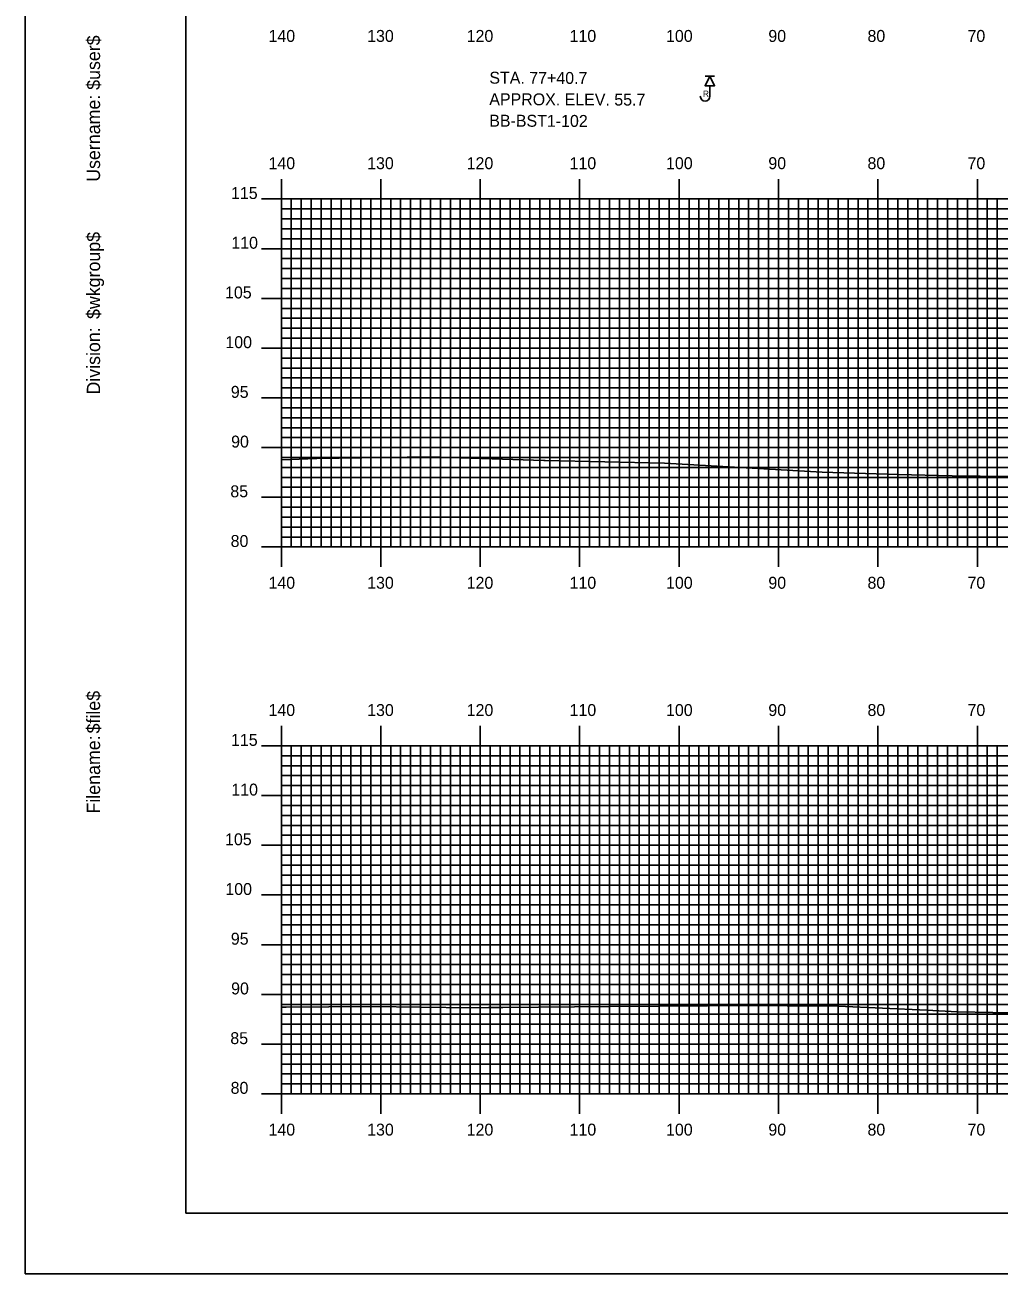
# Model space of a CAD drawing. Extents: x 1761791 to 1762134, y 442591 to 442811.
# Drawn here: x 1761791 to 1761888.9, y 442590.5 to 442716.2 of the extents above; entities that cross this region are included whole.
import ezdxf

# ---------------------------------------------------------------- set-up
doc = ezdxf.new("R2010")
doc.units = 0
for name, color, linetype in [('BORDER', 7, 'Continuous'), ('BORING - REFUSAL', 7, 'Continuous'), ('H_V ANNOTATION', 7, 'Continuous'), ('MAJOR', 7, 'Continuous'), ('MINOR', 7, 'Continuous'), ('PLOT BOUNDARY', 7, 'Continuous'), ('S_Roadway_Centerline', 7, 'Continuous')]:
    doc.layers.add(name, color=color, linetype=linetype)

msp = doc.modelspace()

# ---------------------------------------------------------------- linework, layer by layer
at = {"layer": 'BORDER'}
msp.add_lwpolyline([(1761807.15, 442596.67), (1762127.15, 442596.67), (1762127.15, 442806.67), (1761807.15, 442806.67)], close=True, dxfattribs=at)
at = {"layer": 'BORING - REFUSAL'}
for p, q in [((1761860.33, 442711.02), (1761859.37, 442711.02)), ((1761859.85, 442710.06), (1761859.85, 442709))]:
    msp.add_line(p, q, dxfattribs=at)
msp.add_lwpolyline([(1761859.85, 442711.02), (1761860.33, 442710.06), (1761859.37, 442710.06)], close=True, dxfattribs=at)
msp.add_arc((1761859.37, 442709), 0.485, 180, 0, dxfattribs=at)
at = {"layer": 'MAJOR'}
for p, q in [((1761816.75, 442700.67), (1761816.75, 442698.67)), ((1761826.75, 442700.67), (1761826.75, 442698.67)), ((1761836.75, 442700.67), (1761836.75, 442698.67)), ((1761846.75, 442700.67), (1761846.75, 442698.67)), ((1761856.75, 442700.67), (1761856.75, 442698.67)), ((1761866.75, 442700.67), (1761866.75, 442698.67)), ((1761876.75, 442700.67), (1761876.75, 442698.67)), ((1761886.75, 442700.67), (1761886.75, 442698.67)), ((1761814.75, 442698.67), (1761816.75, 442698.67)), ((1761816.75, 442698.67), (1762096.75, 442698.67)), ((1761816.75, 442663.67), (1761816.75, 442698.67)), ((1761816.75, 442663.67), (1761816.75, 442698.67)), ((1761816.75, 442698.67), (1762096.75, 442698.67)), ((1761826.75, 442663.67), (1761826.75, 442698.67)), ((1761836.75, 442663.67), (1761836.75, 442698.67)), ((1761846.75, 442663.67), (1761846.75, 442698.67)), ((1761856.75, 442663.67), (1761856.75, 442698.67)), ((1761866.75, 442663.67), (1761866.75, 442698.67)), ((1761876.75, 442663.67), (1761876.75, 442698.67)), ((1761886.75, 442663.67), (1761886.75, 442698.67)), ((1761814.75, 442693.67), (1761816.75, 442693.67)), ((1761816.75, 442693.67), (1762096.75, 442693.67)), ((1761814.75, 442688.67), (1761816.75, 442688.67)), ((1761816.75, 442688.67), (1762096.75, 442688.67)), ((1761814.75, 442683.67), (1761816.75, 442683.67)), ((1761816.75, 442683.67), (1762096.75, 442683.67)), ((1761814.75, 442678.67), (1761816.75, 442678.67)), ((1761816.75, 442678.67), (1762096.75, 442678.67)), ((1761814.75, 442673.67), (1761816.75, 442673.67)), ((1761816.75, 442673.67), (1762096.75, 442673.67)), ((1761814.75, 442668.67), (1761816.75, 442668.67)), ((1761816.75, 442668.67), (1762096.75, 442668.67)), ((1761814.75, 442663.67), (1761816.75, 442663.67)), ((1761816.75, 442663.67), (1762096.75, 442663.67)), ((1761816.75, 442663.67), (1762096.75, 442663.67)), ((1761816.75, 442661.66), (1761816.75, 442663.67)), ((1761826.75, 442661.66), (1761826.75, 442663.67)), ((1761836.75, 442661.66), (1761836.75, 442663.67)), ((1761846.75, 442661.66), (1761846.75, 442663.67)), ((1761856.75, 442661.66), (1761856.75, 442663.67)), ((1761866.75, 442661.66), (1761866.75, 442663.67)), ((1761876.75, 442661.66), (1761876.75, 442663.67)), ((1761886.75, 442661.66), (1761886.75, 442663.67)), ((1761816.75, 442645.67), (1761816.75, 442643.67)), ((1761826.75, 442645.67), (1761826.75, 442643.67)), ((1761836.75, 442645.67), (1761836.75, 442643.67)), ((1761846.75, 442645.67), (1761846.75, 442643.67)), ((1761856.75, 442645.67), (1761856.75, 442643.67)), ((1761866.75, 442645.67), (1761866.75, 442643.67)), ((1761876.75, 442645.67), (1761876.75, 442643.67)), ((1761886.75, 442645.67), (1761886.75, 442643.67)), ((1761814.75, 442643.67), (1761816.75, 442643.67)), ((1761816.75, 442643.67), (1762096.75, 442643.67)), ((1761816.75, 442608.67), (1761816.75, 442643.67)), ((1761816.75, 442608.67), (1761816.75, 442643.67)), ((1761816.75, 442643.67), (1762096.75, 442643.67)), ((1761826.75, 442608.67), (1761826.75, 442643.67)), ((1761836.75, 442608.67), (1761836.75, 442643.67)), ((1761846.75, 442608.67), (1761846.75, 442643.67)), ((1761856.75, 442608.67), (1761856.75, 442643.67)), ((1761866.75, 442608.67), (1761866.75, 442643.67)), ((1761876.75, 442608.67), (1761876.75, 442643.67)), ((1761886.75, 442608.67), (1761886.75, 442643.67)), ((1761814.75, 442638.67), (1761816.75, 442638.67)), ((1761816.75, 442638.67), (1762096.75, 442638.67)), ((1761814.75, 442633.67), (1761816.75, 442633.67)), ((1761816.75, 442633.67), (1762096.75, 442633.67)), ((1761814.75, 442628.67), (1761816.75, 442628.67)), ((1761816.75, 442628.67), (1762096.75, 442628.67)), ((1761814.75, 442623.67), (1761816.75, 442623.67)), ((1761816.75, 442623.67), (1762096.75, 442623.67)), ((1761814.75, 442618.67), (1761816.75, 442618.67)), ((1761816.75, 442618.67), (1762096.75, 442618.67)), ((1761814.75, 442613.67), (1761816.75, 442613.67)), ((1761816.75, 442613.67), (1762096.75, 442613.67)), ((1761814.75, 442608.67), (1761816.75, 442608.67)), ((1761816.75, 442608.67), (1762096.75, 442608.67)), ((1761816.75, 442608.67), (1762096.75, 442608.67)), ((1761816.75, 442606.66), (1761816.75, 442608.67)), ((1761826.75, 442606.66), (1761826.75, 442608.67)), ((1761836.75, 442606.66), (1761836.75, 442608.67)), ((1761846.75, 442606.66), (1761846.75, 442608.67)), ((1761856.75, 442606.66), (1761856.75, 442608.67)), ((1761866.75, 442606.66), (1761866.75, 442608.67)), ((1761876.75, 442606.66), (1761876.75, 442608.67)), ((1761886.75, 442606.66), (1761886.75, 442608.67))]:
    msp.add_line(p, q, dxfattribs=at)
at = {"layer": 'MINOR'}
for p, q in [((1761817.75, 442663.67), (1761817.75, 442698.67)), ((1761818.75, 442663.67), (1761818.75, 442698.67)), ((1761819.75, 442663.67), (1761819.75, 442698.67)), ((1761820.75, 442663.67), (1761820.75, 442698.67)), ((1761821.75, 442663.67), (1761821.75, 442698.67)), ((1761822.75, 442663.67), (1761822.75, 442698.67)), ((1761823.75, 442663.67), (1761823.75, 442698.67)), ((1761824.75, 442663.67), (1761824.75, 442698.67)), ((1761825.75, 442663.67), (1761825.75, 442698.67)), ((1761827.75, 442663.67), (1761827.75, 442698.67)), ((1761828.75, 442663.67), (1761828.75, 442698.67)), ((1761829.75, 442663.67), (1761829.75, 442698.67)), ((1761830.75, 442663.67), (1761830.75, 442698.67)), ((1761831.75, 442663.67), (1761831.75, 442698.67)), ((1761832.75, 442663.67), (1761832.75, 442698.67)), ((1761833.75, 442663.67), (1761833.75, 442698.67)), ((1761834.75, 442663.67), (1761834.75, 442698.67)), ((1761835.75, 442663.67), (1761835.75, 442698.67)), ((1761837.75, 442663.67), (1761837.75, 442698.67)), ((1761838.75, 442663.67), (1761838.75, 442698.67)), ((1761839.75, 442663.67), (1761839.75, 442698.67)), ((1761840.75, 442663.67), (1761840.75, 442698.67)), ((1761841.75, 442663.67), (1761841.75, 442698.67)), ((1761842.75, 442663.67), (1761842.75, 442698.67)), ((1761843.75, 442663.67), (1761843.75, 442698.67)), ((1761844.75, 442663.67), (1761844.75, 442698.67)), ((1761845.75, 442663.67), (1761845.75, 442698.67)), ((1761847.75, 442663.67), (1761847.75, 442698.67)), ((1761848.75, 442663.67), (1761848.75, 442698.67)), ((1761849.75, 442663.67), (1761849.75, 442698.67)), ((1761850.75, 442663.67), (1761850.75, 442698.67)), ((1761851.75, 442663.67), (1761851.75, 442698.67)), ((1761852.75, 442663.67), (1761852.75, 442698.67)), ((1761853.75, 442663.67), (1761853.75, 442698.67)), ((1761854.75, 442663.67), (1761854.75, 442698.67)), ((1761855.75, 442663.67), (1761855.75, 442698.67)), ((1761857.75, 442663.67), (1761857.75, 442698.67)), ((1761858.75, 442663.67), (1761858.75, 442698.67)), ((1761859.75, 442663.67), (1761859.75, 442698.67)), ((1761860.75, 442663.67), (1761860.75, 442698.67)), ((1761861.75, 442663.67), (1761861.75, 442698.67)), ((1761862.75, 442663.67), (1761862.75, 442698.67)), ((1761863.75, 442663.67), (1761863.75, 442698.67)), ((1761864.75, 442663.67), (1761864.75, 442698.67)), ((1761865.75, 442663.67), (1761865.75, 442698.67)), ((1761867.75, 442663.67), (1761867.75, 442698.67)), ((1761868.75, 442663.67), (1761868.75, 442698.67)), ((1761869.75, 442663.67), (1761869.75, 442698.67)), ((1761870.75, 442663.67), (1761870.75, 442698.67)), ((1761871.75, 442663.67), (1761871.75, 442698.67)), ((1761872.75, 442663.67), (1761872.75, 442698.67)), ((1761873.75, 442663.67), (1761873.75, 442698.67)), ((1761874.75, 442663.67), (1761874.75, 442698.67)), ((1761875.75, 442663.67), (1761875.75, 442698.67)), ((1761877.75, 442663.67), (1761877.75, 442698.67)), ((1761878.75, 442663.67), (1761878.75, 442698.67)), ((1761879.75, 442663.67), (1761879.75, 442698.67)), ((1761880.75, 442663.67), (1761880.75, 442698.67)), ((1761881.75, 442663.67), (1761881.75, 442698.67)), ((1761882.75, 442663.67), (1761882.75, 442698.67)), ((1761883.75, 442663.67), (1761883.75, 442698.67)), ((1761884.75, 442663.67), (1761884.75, 442698.67)), ((1761885.75, 442663.67), (1761885.75, 442698.67)), ((1761887.75, 442663.67), (1761887.75, 442698.67)), ((1761888.75, 442663.67), (1761888.75, 442698.67)), ((1761816.75, 442697.67), (1762096.75, 442697.67)), ((1761816.75, 442697.67), (1761818.76, 442697.67)), ((1761816.75, 442696.67), (1762096.75, 442696.67)), ((1761816.75, 442696.67), (1761818.76, 442696.67)), ((1761816.75, 442695.67), (1762096.75, 442695.67)), ((1761816.75, 442695.67), (1761818.76, 442695.67)), ((1761816.75, 442694.67), (1762096.75, 442694.67)), ((1761816.75, 442694.67), (1761818.76, 442694.67)), ((1761816.75, 442692.67), (1762096.75, 442692.67)), ((1761816.75, 442692.67), (1761818.76, 442692.67)), ((1761816.75, 442691.67), (1762096.75, 442691.67)), ((1761816.75, 442691.67), (1761818.76, 442691.67)), ((1761816.75, 442690.67), (1762096.75, 442690.67)), ((1761816.75, 442690.67), (1761818.76, 442690.67)), ((1761816.75, 442689.67), (1762096.75, 442689.67)), ((1761816.75, 442689.67), (1761818.76, 442689.67)), ((1761816.75, 442687.67), (1762096.75, 442687.67)), ((1761816.75, 442687.67), (1761818.76, 442687.67)), ((1761816.75, 442686.67), (1762096.75, 442686.67)), ((1761816.75, 442686.67), (1761818.76, 442686.67)), ((1761816.75, 442685.67), (1762096.75, 442685.67)), ((1761816.75, 442685.67), (1761818.76, 442685.67)), ((1761816.75, 442684.67), (1762096.75, 442684.67)), ((1761816.75, 442684.67), (1761818.76, 442684.67)), ((1761816.75, 442682.67), (1762096.75, 442682.67)), ((1761816.75, 442682.67), (1761818.76, 442682.67)), ((1761816.75, 442681.67), (1762096.75, 442681.67)), ((1761816.75, 442681.67), (1761818.76, 442681.67)), ((1761816.75, 442680.67), (1762096.75, 442680.67)), ((1761816.75, 442680.67), (1761818.76, 442680.67)), ((1761816.75, 442679.67), (1762096.75, 442679.67)), ((1761816.75, 442679.67), (1761818.76, 442679.67)), ((1761816.75, 442677.67), (1762096.75, 442677.67)), ((1761816.75, 442677.67), (1761818.76, 442677.67)), ((1761816.75, 442676.67), (1762096.75, 442676.67)), ((1761816.75, 442676.67), (1761818.76, 442676.67)), ((1761816.75, 442675.67), (1762096.75, 442675.67)), ((1761816.75, 442675.67), (1761818.76, 442675.67)), ((1761816.75, 442674.67), (1762096.75, 442674.67)), ((1761816.75, 442674.67), (1761818.76, 442674.67)), ((1761816.75, 442672.67), (1762096.75, 442672.67)), ((1761816.75, 442672.67), (1761818.76, 442672.67)), ((1761816.75, 442671.67), (1762096.75, 442671.67)), ((1761816.75, 442671.67), (1761818.76, 442671.67)), ((1761816.75, 442670.67), (1762096.75, 442670.67)), ((1761816.75, 442670.67), (1761818.76, 442670.67)), ((1761816.75, 442669.67), (1762096.75, 442669.67)), ((1761816.75, 442669.67), (1761818.76, 442669.67)), ((1761816.75, 442667.67), (1762096.75, 442667.67)), ((1761816.75, 442667.67), (1761818.76, 442667.67)), ((1761816.75, 442666.67), (1762096.75, 442666.67)), ((1761816.75, 442666.67), (1761818.76, 442666.67)), ((1761816.75, 442665.67), (1762096.75, 442665.67)), ((1761816.75, 442665.67), (1761818.76, 442665.67)), ((1761816.75, 442664.67), (1762096.75, 442664.67)), ((1761816.75, 442664.67), (1761818.76, 442664.67)), ((1761817.75, 442608.67), (1761817.75, 442643.67)), ((1761818.75, 442608.67), (1761818.75, 442643.67)), ((1761819.75, 442608.67), (1761819.75, 442643.67)), ((1761820.75, 442608.67), (1761820.75, 442643.67)), ((1761821.75, 442608.67), (1761821.75, 442643.67)), ((1761822.75, 442608.67), (1761822.75, 442643.67)), ((1761823.75, 442608.67), (1761823.75, 442643.67)), ((1761824.75, 442608.67), (1761824.75, 442643.67)), ((1761825.75, 442608.67), (1761825.75, 442643.67)), ((1761827.75, 442608.67), (1761827.75, 442643.67)), ((1761828.75, 442608.67), (1761828.75, 442643.67)), ((1761829.75, 442608.67), (1761829.75, 442643.67)), ((1761830.75, 442608.67), (1761830.75, 442643.67)), ((1761831.75, 442608.67), (1761831.75, 442643.67)), ((1761832.75, 442608.67), (1761832.75, 442643.67)), ((1761833.75, 442608.67), (1761833.75, 442643.67)), ((1761834.75, 442608.67), (1761834.75, 442643.67)), ((1761835.75, 442608.67), (1761835.75, 442643.67)), ((1761837.75, 442608.67), (1761837.75, 442643.67)), ((1761838.75, 442608.67), (1761838.75, 442643.67)), ((1761839.75, 442608.67), (1761839.75, 442643.67)), ((1761840.75, 442608.67), (1761840.75, 442643.67)), ((1761841.75, 442608.67), (1761841.75, 442643.67)), ((1761842.75, 442608.67), (1761842.75, 442643.67)), ((1761843.75, 442608.67), (1761843.75, 442643.67)), ((1761844.75, 442608.67), (1761844.75, 442643.67)), ((1761845.75, 442608.67), (1761845.75, 442643.67)), ((1761847.75, 442608.67), (1761847.75, 442643.67)), ((1761848.75, 442608.67), (1761848.75, 442643.67)), ((1761849.75, 442608.67), (1761849.75, 442643.67)), ((1761850.75, 442608.67), (1761850.75, 442643.67)), ((1761851.75, 442608.67), (1761851.75, 442643.67)), ((1761852.75, 442608.67), (1761852.75, 442643.67)), ((1761853.75, 442608.67), (1761853.75, 442643.67)), ((1761854.75, 442608.67), (1761854.75, 442643.67)), ((1761855.75, 442608.67), (1761855.75, 442643.67)), ((1761857.75, 442608.67), (1761857.75, 442643.67)), ((1761858.75, 442608.67), (1761858.75, 442643.67)), ((1761859.75, 442608.67), (1761859.75, 442643.67)), ((1761860.75, 442608.67), (1761860.75, 442643.67)), ((1761861.75, 442608.67), (1761861.75, 442643.67)), ((1761862.75, 442608.67), (1761862.75, 442643.67)), ((1761863.75, 442608.67), (1761863.75, 442643.67)), ((1761864.75, 442608.67), (1761864.75, 442643.67)), ((1761865.75, 442608.67), (1761865.75, 442643.67)), ((1761867.75, 442608.67), (1761867.75, 442643.67)), ((1761868.75, 442608.67), (1761868.75, 442643.67)), ((1761869.75, 442608.67), (1761869.75, 442643.67)), ((1761870.75, 442608.67), (1761870.75, 442643.67)), ((1761871.75, 442608.67), (1761871.75, 442643.67)), ((1761872.75, 442608.67), (1761872.75, 442643.67)), ((1761873.75, 442608.67), (1761873.75, 442643.67)), ((1761874.75, 442608.67), (1761874.75, 442643.67)), ((1761875.75, 442608.67), (1761875.75, 442643.67)), ((1761877.75, 442608.67), (1761877.75, 442643.67)), ((1761878.75, 442608.67), (1761878.75, 442643.67)), ((1761879.75, 442608.67), (1761879.75, 442643.67)), ((1761880.75, 442608.67), (1761880.75, 442643.67)), ((1761881.75, 442608.67), (1761881.75, 442643.67)), ((1761882.75, 442608.67), (1761882.75, 442643.67)), ((1761883.75, 442608.67), (1761883.75, 442643.67)), ((1761884.75, 442608.67), (1761884.75, 442643.67)), ((1761885.75, 442608.67), (1761885.75, 442643.67)), ((1761887.75, 442608.67), (1761887.75, 442643.67)), ((1761888.75, 442608.67), (1761888.75, 442643.67)), ((1761816.75, 442642.67), (1762096.75, 442642.67)), ((1761816.75, 442642.67), (1761818.76, 442642.67)), ((1761816.75, 442641.67), (1762096.75, 442641.67)), ((1761816.75, 442641.67), (1761818.76, 442641.67)), ((1761816.75, 442640.67), (1762096.75, 442640.67)), ((1761816.75, 442640.67), (1761818.76, 442640.67)), ((1761816.75, 442639.67), (1762096.75, 442639.67)), ((1761816.75, 442639.67), (1761818.76, 442639.67)), ((1761816.75, 442637.67), (1762096.75, 442637.67)), ((1761816.75, 442637.67), (1761818.76, 442637.67)), ((1761816.75, 442636.67), (1762096.75, 442636.67)), ((1761816.75, 442636.67), (1761818.76, 442636.67)), ((1761816.75, 442635.67), (1762096.75, 442635.67)), ((1761816.75, 442635.67), (1761818.76, 442635.67)), ((1761816.75, 442634.67), (1762096.75, 442634.67)), ((1761816.75, 442634.67), (1761818.76, 442634.67)), ((1761816.75, 442632.67), (1762096.75, 442632.67)), ((1761816.75, 442632.67), (1761818.76, 442632.67)), ((1761816.75, 442631.67), (1762096.75, 442631.67)), ((1761816.75, 442631.67), (1761818.76, 442631.67)), ((1761816.75, 442630.67), (1762096.75, 442630.67)), ((1761816.75, 442630.67), (1761818.76, 442630.67)), ((1761816.75, 442629.67), (1762096.75, 442629.67)), ((1761816.75, 442629.67), (1761818.76, 442629.67)), ((1761816.75, 442627.67), (1762096.75, 442627.67)), ((1761816.75, 442627.67), (1761818.76, 442627.67)), ((1761816.75, 442626.67), (1762096.75, 442626.67)), ((1761816.75, 442626.67), (1761818.76, 442626.67)), ((1761816.75, 442625.67), (1762096.75, 442625.67)), ((1761816.75, 442625.67), (1761818.76, 442625.67)), ((1761816.75, 442624.67), (1762096.75, 442624.67)), ((1761816.75, 442624.67), (1761818.76, 442624.67)), ((1761816.75, 442622.67), (1762096.75, 442622.67)), ((1761816.75, 442622.67), (1761818.76, 442622.67)), ((1761816.75, 442621.67), (1762096.75, 442621.67)), ((1761816.75, 442621.67), (1761818.76, 442621.67)), ((1761816.75, 442620.67), (1762096.75, 442620.67)), ((1761816.75, 442620.67), (1761818.76, 442620.67)), ((1761816.75, 442619.67), (1762096.75, 442619.67)), ((1761816.75, 442619.67), (1761818.76, 442619.67)), ((1761816.75, 442617.67), (1762096.75, 442617.67)), ((1761816.75, 442617.67), (1761818.76, 442617.67)), ((1761816.75, 442616.67), (1762096.75, 442616.67)), ((1761816.75, 442616.67), (1761818.76, 442616.67)), ((1761816.75, 442615.67), (1762096.75, 442615.67)), ((1761816.75, 442615.67), (1761818.76, 442615.67)), ((1761816.75, 442614.67), (1762096.75, 442614.67)), ((1761816.75, 442614.67), (1761818.76, 442614.67)), ((1761816.75, 442612.67), (1762096.75, 442612.67)), ((1761816.75, 442612.67), (1761818.76, 442612.67)), ((1761816.75, 442611.67), (1762096.75, 442611.67)), ((1761816.75, 442611.67), (1761818.76, 442611.67)), ((1761816.75, 442610.67), (1762096.75, 442610.67)), ((1761816.75, 442610.67), (1761818.76, 442610.67)), ((1761816.75, 442609.67), (1762096.75, 442609.67)), ((1761816.75, 442609.67), (1761818.76, 442609.67))]:
    msp.add_line(p, q, dxfattribs=at)
at = {"layer": 'PLOT BOUNDARY'}
msp.add_lwpolyline([(1761790.97, 442590.55), (1762130.97, 442590.55), (1762130.97, 442810.55), (1761790.97, 442810.55)], close=True, dxfattribs=at)
at = {"layer": 'S_Roadway_Centerline'}
for points in [[(1761816.75, 442672.44), (1761820.33, 442672.56), (1761822.58, 442672.59), (1761831.67, 442672.73), (1761843.16, 442672.37), (1761843.29, 442672.36), (1761855.28, 442672.1), (1761871.14, 442671.21), (1761878.76, 442670.97), (1761884.22, 442670.83), (1761889.89, 442670.77)], [(1761816.75, 442617.38), (1761817.22, 442617.37), (1761825.81, 442617.44), (1761835.8, 442617.33), (1761837.59, 442617.35), (1761839.04, 442617.35), (1761849.82, 442617.45), (1761859.61, 442617.53), (1761862.48, 442617.54), (1761872.75, 442617.49), (1761881.68, 442617.08), (1761884.72, 442616.92), (1761888.3, 442616.86), (1761896.19, 442616.69)]]:
    msp.add_lwpolyline(points, dxfattribs=at)

# ---------------------------------------------------------------- texts
at = {"layer": 'BORDER'}
for s, p in [('$user$', (1761798.52, 442709.65)), ('Username:', (1761798.52, 442700.4)), ('$wkgroup$', (1761798.52, 442686.6)), ('Division:', (1761798.52, 442679)), ('$file$', (1761798.52, 442644.92)), ('Filename:', (1761798.52, 442636.86))]:
    msp.add_text(s, height=1.339, rotation=90, dxfattribs=at).set_placement(p)
at = {"layer": 'BORING - REFUSAL'}
for s, p in [('STA. 77+40.7', (1761837.67, 442710.27)), ('APPROX. ELEV. 55.7', (1761837.66, 442708.11)), ('BB-BST1-102', (1761837.66, 442705.95))]:
    msp.add_text(s, height=1.2, rotation=359.8142, dxfattribs=at).set_placement(p)
msp.add_text('R', height=0.64, dxfattribs=at).set_placement((1761859.14, 442708.94))
at = {"layer": 'H_V ANNOTATION'}
for s, p in [('140', (1761815.46, 442714.47)), ('130', (1761825.38, 442714.47)), ('120', (1761835.39, 442714.47)), ('110', (1761845.74, 442714.47)), ('100', (1761855.44, 442714.47)), ('90', (1761865.73, 442714.47)), ('80', (1761875.7, 442714.47)), ('70', (1761885.76, 442714.47)), ('140', (1761815.46, 442701.67)), ('130', (1761825.38, 442701.67)), ('120', (1761835.39, 442701.67)), ('110', (1761845.74, 442701.67)), ('100', (1761855.44, 442701.67)), ('90', (1761865.73, 442701.67)), ('80', (1761875.7, 442701.67)), ('70', (1761885.76, 442701.67)), ('115', (1761811.69, 442698.67)), ('110', (1761811.72, 442693.67)), ('105', (1761811.09, 442688.67)), ('100', (1761811.12, 442683.67)), ('95', (1761811.67, 442678.67)), ('90', (1761811.7, 442673.67)), ('85', (1761811.62, 442668.67)), ('80', (1761811.65, 442663.67)), ('140', (1761815.46, 442659.47)), ('130', (1761825.38, 442659.47)), ('120', (1761835.39, 442659.47)), ('110', (1761845.74, 442659.47)), ('100', (1761855.44, 442659.47)), ('90', (1761865.73, 442659.47)), ('80', (1761875.7, 442659.47)), ('70', (1761885.76, 442659.47)), ('140', (1761815.46, 442646.67)), ('130', (1761825.38, 442646.67)), ('120', (1761835.39, 442646.67)), ('110', (1761845.74, 442646.67)), ('100', (1761855.44, 442646.67)), ('90', (1761865.73, 442646.67)), ('80', (1761875.7, 442646.67)), ('70', (1761885.76, 442646.67)), ('115', (1761811.69, 442643.67)), ('110', (1761811.72, 442638.67)), ('105', (1761811.09, 442633.67)), ('100', (1761811.12, 442628.67)), ('95', (1761811.67, 442623.67)), ('90', (1761811.7, 442618.67)), ('85', (1761811.62, 442613.67)), ('80', (1761811.65, 442608.67)), ('140', (1761815.46, 442604.47)), ('130', (1761825.38, 442604.47)), ('120', (1761835.39, 442604.47)), ('110', (1761845.74, 442604.47)), ('100', (1761855.44, 442604.47)), ('90', (1761865.73, 442604.47)), ('80', (1761875.7, 442604.47)), ('70', (1761885.76, 442604.47))]:
    msp.add_text(s, height=1.2, dxfattribs=at).set_placement(p)
at = {"layer": 'MAJOR'}
for p in [(1761816.74, 442663.67), (1761816.74, 442608.67)]:
    msp.add_text('-', height=0.012, dxfattribs=at).set_placement(p)

doc.saveas('drawing.dxf')
